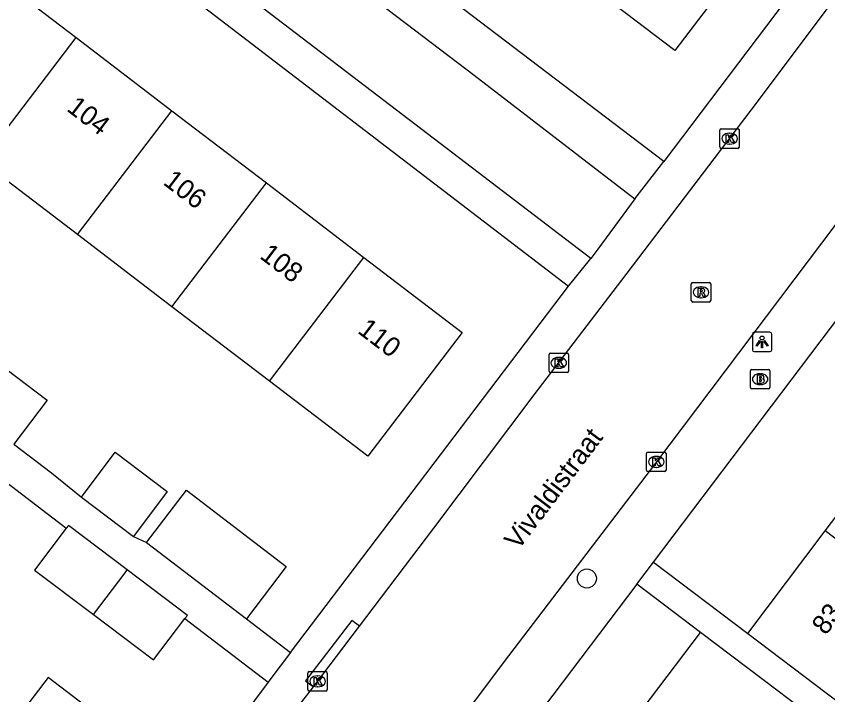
# Model space of a CAD drawing. Extents: x 159040 to 160094, y 381214 to 382518.
# Drawn here: x 159350 to 159391.67, y 381935.45 to 381970.26 of the extents above; entities that cross this region are included whole.
import ezdxf

# ---------------------------------------------------------------- set-up
doc = ezdxf.new("R2010")
doc.units = 0
for name, color, linetype in [('IMGEO_Boom', 7, 'Continuous'), ('IMGEO_Brandkraan', 7, 'Continuous'), ('IMGEO_Kolk', 7, 'Continuous'), ('IMGEO_Lichtpunt', 7, 'Continuous'), ('IMGEO_Openbare_ruimte_label', 7, 'Continuous'), ('IMGEO_Pand', 7, 'Continuous'), ('IMGEO_Pand_nummerreeks', 7, 'Continuous'), ('IMGEO_Rijbaan_lokaal_open', 7, 'Continuous'), ('IMGEO_Rioolput', 7, 'Continuous'), ('IMGEO_Voetpad_open', 7, 'Continuous')]:
    doc.layers.add(name, color=color, linetype=linetype)

msp = doc.modelspace()

# ---------------------------------------------------------------- linework, layer by layer
at = {"layer": 'IMGEO_Boom'}
msp.add_circle((159379.303, 381941.411), 0.489, dxfattribs=at)
at = {"layer": 'IMGEO_Brandkraan'}
for p, q in [((159387.776, 381952.139), (159388.628, 381952.139)), ((159387.701, 381951.213), (159387.701, 381952.065)), ((159388.189, 381951.919), (159388.214, 381951.919)), ((159388.702, 381952.065), (159388.702, 381951.213)), ((159388.212, 381951.359), (159388.187, 381951.359)), ((159388.628, 381951.139), (159387.776, 381951.139))]:
    msp.add_line(p, q, dxfattribs=at)
for points in [[(159387.776, 381952.139), (159388.628, 381952.139)], [(159387.701, 381951.213), (159387.701, 381952.065)], [(159388.049, 381951.839), (159388.049, 381951.439), (159388.262, 381951.439)], [(159388.28, 381951.839), (159388.049, 381951.839)], [(159388.228, 381951.758), (159388.174, 381951.758), (159388.174, 381951.682)], [(159388.702, 381952.065), (159388.702, 381951.213)], [(159388.174, 381951.682), (159388.227, 381951.682)], [(159388.236, 381951.606), (159388.174, 381951.606), (159388.174, 381951.525)], [(159388.174, 381951.525), (159388.236, 381951.525)], [(159388.628, 381951.139), (159387.776, 381951.139)]]:
    msp.add_lwpolyline(points, dxfattribs=at)
for centre, radius, start, end in [((159387.778, 381952.063), 0.0765, 91.552, 178.448), ((159387.778, 381952.063), 0.0765, 91.552, 178.448), ((159388.626, 381952.063), 0.0765, 1.552, 88.448), ((159388.626, 381952.063), 0.0765, 1.552, 88.448), ((159388.229, 381951.72), 0.0379, 267.8285, 90.9355), ((159388.284, 381951.694), 0.145, 59.4692, 91.5367), ((159388.309, 381951.741), 0.0922, 285.5137, 58.1501), ((159388.237, 381951.565), 0.0404, 269.8759, 90.5077), ((159388.268, 381951.69), 0.251, 268.6676, 293.5347), ((159388.314, 381951.549), 0.105, 301.3115, 78.989), ((159387.778, 381951.215), 0.0765, 181.552, 268.448), ((159387.778, 381951.215), 0.0765, 181.552, 268.448), ((159388.626, 381951.215), 0.0765, 271.552, 358.448), ((159388.626, 381951.215), 0.0765, 271.552, 358.448)]:
    msp.add_arc(centre, radius, start, end, dxfattribs=at)
for centre, major_axis, ratio, start_param, end_param in [((159388.188, 381951.639), (-0.387, 0.002), 0.722429, 4.712389, 7.853982), ((159388.213, 381951.639), (-0.39, 0.002), 0.717154, 1.570796, 4.712389)]:
    msp.add_ellipse(centre, major_axis=major_axis, ratio=ratio, start_param=start_param, end_param=end_param, dxfattribs=at)
at = {"layer": 'IMGEO_Kolk'}
for p, q in [((159386.131, 381963.556), (159386.131, 381964.408)), ((159386.206, 381964.482), (159387.058, 381964.482)), ((159386.619, 381964.262), (159386.644, 381964.262)), ((159387.132, 381964.408), (159387.132, 381963.556)), ((159387.058, 381963.482), (159386.206, 381963.482)), ((159386.642, 381963.702), (159386.617, 381963.702)), ((159377.436, 381952.976), (159378.288, 381952.976)), ((159377.361, 381952.05), (159377.361, 381952.902)), ((159377.849, 381952.756), (159377.874, 381952.756)), ((159378.362, 381952.902), (159378.362, 381952.05)), ((159377.872, 381952.196), (159377.847, 381952.196)), ((159378.288, 381951.976), (159377.436, 381951.976)), ((159382.368, 381946.968), (159382.368, 381947.82)), ((159382.443, 381947.894), (159383.295, 381947.894)), ((159382.856, 381947.674), (159382.881, 381947.674)), ((159383.369, 381947.82), (159383.369, 381946.968)), ((159383.295, 381946.894), (159382.443, 381946.894)), ((159382.879, 381947.114), (159382.854, 381947.114)), ((159364.975, 381935.709), (159364.975, 381936.561)), ((159365.05, 381936.635), (159365.902, 381936.635)), ((159365.463, 381936.415), (159365.488, 381936.415)), ((159365.976, 381936.561), (159365.976, 381935.709)), ((159365.902, 381935.635), (159365.05, 381935.635)), ((159365.486, 381935.855), (159365.461, 381935.855))]:
    msp.add_line(p, q, dxfattribs=at)
for points in [[(159386.131, 381963.556), (159386.131, 381964.408)], [(159386.206, 381964.482), (159387.058, 381964.482)], [(159387.132, 381964.408), (159387.132, 381963.556)], [(159386.452, 381964.182), (159386.575, 381964.182), (159386.575, 381964.031), (159386.705, 381964.182), (159386.869, 381964.182), (159386.723, 381964.031), (159386.876, 381963.782), (159386.724, 381963.782), (159386.639, 381963.946), (159386.575, 381963.879), (159386.575, 381963.782), (159386.452, 381963.782), (159386.452, 381964.182)], [(159387.058, 381963.482), (159386.206, 381963.482)], [(159377.436, 381952.976), (159378.288, 381952.976)], [(159377.361, 381952.05), (159377.361, 381952.902)], [(159377.682, 381952.676), (159377.805, 381952.676), (159377.805, 381952.525), (159377.935, 381952.676), (159378.099, 381952.676), (159377.953, 381952.525), (159378.106, 381952.276), (159377.954, 381952.276), (159377.869, 381952.44), (159377.805, 381952.373), (159377.805, 381952.276), (159377.682, 381952.276), (159377.682, 381952.676)], [(159378.362, 381952.902), (159378.362, 381952.05)], [(159378.288, 381951.976), (159377.436, 381951.976)], [(159382.368, 381946.968), (159382.368, 381947.82)], [(159382.443, 381947.894), (159383.295, 381947.894)], [(159382.689, 381947.594), (159382.812, 381947.594), (159382.812, 381947.443), (159382.942, 381947.594), (159383.106, 381947.594), (159382.96, 381947.443), (159383.113, 381947.194), (159382.961, 381947.194), (159382.876, 381947.358), (159382.812, 381947.291), (159382.812, 381947.194), (159382.689, 381947.194), (159382.689, 381947.594)], [(159383.369, 381947.82), (159383.369, 381946.968)], [(159383.295, 381946.894), (159382.443, 381946.894)], [(159364.975, 381935.709), (159364.975, 381936.561)], [(159365.05, 381936.635), (159365.902, 381936.635)], [(159365.296, 381936.335), (159365.419, 381936.335), (159365.419, 381936.184), (159365.549, 381936.335), (159365.713, 381936.335), (159365.567, 381936.184), (159365.72, 381935.935), (159365.568, 381935.935), (159365.483, 381936.099), (159365.419, 381936.032), (159365.419, 381935.935), (159365.296, 381935.935), (159365.296, 381936.335)], [(159365.976, 381936.561), (159365.976, 381935.709)], [(159365.902, 381935.635), (159365.05, 381935.635)]]:
    msp.add_lwpolyline(points, dxfattribs=at)
for centre, start, end in [((159386.208, 381964.406), 91.552, 178.448), ((159386.208, 381964.406), 91.552, 178.448), ((159387.056, 381964.406), 1.552, 88.448), ((159387.056, 381964.406), 1.552, 88.448), ((159386.208, 381963.558), 181.552, 268.448), ((159386.208, 381963.558), 181.552, 268.448), ((159387.056, 381963.558), 271.552, 358.448), ((159387.056, 381963.558), 271.552, 358.448), ((159377.438, 381952.9), 91.552, 178.448), ((159377.438, 381952.9), 91.552, 178.448), ((159378.286, 381952.9), 1.552, 88.448), ((159378.286, 381952.9), 1.552, 88.448), ((159377.438, 381952.052), 181.552, 268.448), ((159377.438, 381952.052), 181.552, 268.448), ((159378.286, 381952.052), 271.552, 358.448), ((159378.286, 381952.052), 271.552, 358.448), ((159382.445, 381947.818), 91.552, 178.448), ((159382.445, 381947.818), 91.552, 178.448), ((159383.293, 381947.818), 1.552, 88.448), ((159383.293, 381947.818), 1.552, 88.448), ((159382.445, 381946.97), 181.552, 268.448), ((159382.445, 381946.97), 181.552, 268.448), ((159383.293, 381946.97), 271.552, 358.448), ((159383.293, 381946.97), 271.552, 358.448), ((159365.052, 381936.559), 91.552, 178.448), ((159365.052, 381936.559), 91.552, 178.448), ((159365.9, 381936.559), 1.552, 88.448), ((159365.9, 381936.559), 1.552, 88.448), ((159365.052, 381935.711), 181.552, 268.448), ((159365.052, 381935.711), 181.552, 268.448), ((159365.9, 381935.711), 271.552, 358.448), ((159365.9, 381935.711), 271.552, 358.448)]:
    msp.add_arc(centre, 0.0765, start, end, dxfattribs=at)
for centre, major_axis, ratio, start_param, end_param in [((159386.618, 381963.982), (-0.387, 0.002), 0.722429, 4.712389, 7.853982), ((159386.643, 381963.982), (-0.39, 0.002), 0.717154, 1.570796, 4.712389), ((159377.848, 381952.476), (-0.387, 0.002), 0.722429, 4.712389, 7.853982), ((159377.873, 381952.476), (-0.39, 0.002), 0.717154, 1.570796, 4.712389), ((159382.855, 381947.394), (-0.387, 0.002), 0.722429, 4.712389, 7.853982), ((159382.88, 381947.394), (-0.39, 0.002), 0.717154, 1.570796, 4.712389), ((159365.462, 381936.135), (-0.387, 0.002), 0.722429, 4.712389, 7.853982), ((159365.487, 381936.135), (-0.39, 0.002), 0.717154, 1.570796, 4.712389)]:
    msp.add_ellipse(centre, major_axis=major_axis, ratio=ratio, start_param=start_param, end_param=end_param, dxfattribs=at)
at = {"layer": 'IMGEO_Lichtpunt'}
for p, q in [((159387.801, 381953.953), (159387.801, 381953.146)), ((159387.801, 381953.953), (159387.801, 381953.146)), ((159388.703, 381954.048), (159387.895, 381954.048)), ((159388.703, 381954.048), (159387.895, 381954.048)), ((159388.797, 381953.146), (159388.797, 381953.953)), ((159388.797, 381953.146), (159388.797, 381953.953)), ((159387.895, 381953.052), (159388.703, 381953.052)), ((159387.895, 381953.052), (159388.703, 381953.052))]:
    msp.add_line(p, q, dxfattribs=at)
for points in [[(159388.175, 381953.617), (159388.214, 381953.589), (159388.026, 381953.327), (159387.988, 381953.354), (159388.175, 381953.617)], [(159388.277, 381953.569), (159388.324, 381953.569), (159388.324, 381953.247), (159388.277, 381953.247), (159388.277, 381953.569)], [(159388.387, 381953.589), (159388.425, 381953.616), (159388.612, 381953.354), (159388.573, 381953.326), (159388.387, 381953.589)]]:
    msp.add_lwpolyline(points, dxfattribs=at)
msp.add_circle((159388.3, 381953.751), 0.0994, dxfattribs=at)
for centre, start, end in [((159387.895, 381953.953), 90, 180), ((159387.895, 381953.953), 90, 180), ((159388.703, 381953.953), 0, 90), ((159388.703, 381953.953), 0, 90), ((159387.895, 381953.146), 180, 270), ((159387.895, 381953.146), 180, 270), ((159388.703, 381953.146), 270, 0), ((159388.703, 381953.146), 270, 360)]:
    msp.add_arc(centre, 0.0946, start, end, dxfattribs=at)
at = {"layer": 'IMGEO_Pand'}
for points in [[(159383.811, 381979.06), (159388.906, 381975.173), (159383.816, 381968.501), (159378.72, 381972.389)], [(159347.407, 381973.488), (159347.838, 381973.159), (159353.074, 381969.165)], [(159348.226, 381962.81), (159353.074, 381969.165)], [(159353.074, 381969.165), (159357.993, 381965.412)], [(159353.145, 381959.057), (159357.993, 381965.412)], [(159357.993, 381965.412), (159362.847, 381961.708)], [(159353.145, 381959.057), (159348.226, 381962.81)], [(159357.999, 381955.354), (159362.847, 381961.708)], [(159362.847, 381961.708), (159367.855, 381957.888)], [(159357.999, 381955.354), (159353.145, 381959.057)], [(159367.855, 381957.888), (159372.898, 381954.04), (159368.05, 381947.686), (159363.007, 381951.533)], [(159363.007, 381951.533), (159367.855, 381957.888)], [(159363.007, 381951.533), (159357.999, 381955.354)], [(159348.463, 381952.919), (159351.588, 381950.556), (159349.879, 381948.295)], [(159391.54, 381943.85), (159395.265, 381948.769)], [(159353.352, 381945.577), (159355.089, 381947.888), (159357.757, 381945.882), (159356.02, 381943.572)], [(159356.692, 381943.254), (159358.738, 381945.935), (159363.866, 381942.023), (159361.82, 381939.341)], [(159353.352, 381945.577), (159356.02, 381943.572)], [(159352.571, 381943.995), (159350.945, 381941.845), (159353.963, 381939.563)], [(159355.707, 381941.849), (159352.679, 381944.138), (159352.571, 381943.995)], [(159387.562, 381938.595), (159391.54, 381943.85)], [(159396.861, 381939.821), (159391.54, 381943.85)], [(159356.692, 381943.254), (159361.82, 381939.341)], [(159353.963, 381939.563), (159355.588, 381941.693), (159355.707, 381941.849)], [(159358.66, 381939.35), (159358.789, 381939.519), (159355.707, 381941.849)], [(159353.963, 381939.563), (159357.045, 381937.233), (159358.66, 381939.35)], [(159381.285, 381933.558), (159385.134, 381938.642)], [(159391.603, 381933.745), (159389.12, 381935.624), (159385.134, 381938.642)], [(159387.562, 381938.595), (159391.585, 381935.549), (159392.883, 381934.567)], [(159344.161, 381926.714), (159349.244, 381922.836), (159354.423, 381929.625), (159356.635, 381932.524), (159351.641, 381936.334), (159349.429, 381933.435), (159349.34, 381933.503)]]:
    msp.add_lwpolyline(points, dxfattribs=at)
at = {"layer": 'IMGEO_Rijbaan_lokaal_open'}
for points in [[(159367.623, 381938.959), (159371.448, 381943.987), (159376.604, 381950.827), (159381.096, 381956.711), (159383.665, 381960.085), (159387.743, 381965.439), (159395.307, 381975.538), (159400.92, 381983.103), (159405.076, 381988.584)], [(159410.86, 381984.24), (159405.257, 381976.785), (159392.08, 381959.597), (159382.82, 381947.331), (159375.274, 381937.448), (159369.627, 381929.935), (159365.099, 381923.996), (159363.697, 381922.105)], [(159354.4, 381981.799), (159364.253, 381974.292), (159373.522, 381967.236), (159381.764, 381960.886)], [(159379.509, 381957.83), (159352.11, 381978.74), (159352.56, 381979.34)], [(159381.764, 381960.886), (159379.871, 381958.305), (159379.509, 381957.83)], [(159365.26, 381935.852), (159367.623, 381938.959)], [(159358.041, 381926.414), (159361.248, 381930.665), (159364.911, 381935.394), (159365.26, 381935.852)]]:
    msp.add_lwpolyline(points, dxfattribs=at)
at = {"layer": 'IMGEO_Rioolput'}
for p, q in [((159384.663, 381955.67), (159384.663, 381956.522)), ((159384.738, 381956.596), (159385.59, 381956.596)), ((159385.151, 381956.376), (159385.176, 381956.376)), ((159385.664, 381956.522), (159385.664, 381955.67)), ((159385.59, 381955.596), (159384.738, 381955.596)), ((159385.174, 381955.816), (159385.149, 381955.816))]:
    msp.add_line(p, q, dxfattribs=at)
for points in [[(159384.663, 381955.67), (159384.663, 381956.522)], [(159384.738, 381956.596), (159385.59, 381956.596)], [(159385.252, 381956.294), (159385, 381956.296), (159385, 381955.896)], [(159385.664, 381956.522), (159385.664, 381955.67)], [(159385, 381955.896), (159385.124, 381955.896), (159385.124, 381956.058), (159385.135, 381956.058)], [(159385.178, 381956.215), (159385.124, 381956.215), (159385.124, 381956.134)], [(159385.124, 381956.134), (159385.176, 381956.134)], [(159385.182, 381956.029), (159385.253, 381955.896), (159385.393, 381955.896), (159385.328, 381956.022)], [(159385.59, 381955.596), (159384.738, 381955.596)]]:
    msp.add_lwpolyline(points, dxfattribs=at)
for centre, radius, start, end in [((159384.74, 381956.52), 0.0765, 91.552, 178.448), ((159384.74, 381956.52), 0.0765, 91.552, 178.448), ((159385.588, 381956.52), 0.0765, 1.552, 88.448), ((159385.588, 381956.52), 0.0765, 1.552, 88.448), ((159385.134, 381956.005), 0.0533, 26.0293, 88.6989), ((159385.16, 381956.323), 0.19, 274.7715, 282.9687), ((159385.184, 381956.119), 0.0964, 77.0061, 93.1865), ((159385.198, 381956.176), 0.0378, 276.6634, 79.6772), ((159385.251, 381956.184), 0.109, 350.3612, 89.416), ((159385.249, 381956.184), 0.112, 277.5842, 350.9817), ((159385.233, 381955.969), 0.108, 29.5134, 73.7905), ((159384.74, 381955.672), 0.0765, 181.552, 268.448), ((159384.74, 381955.672), 0.0765, 181.552, 268.448), ((159385.588, 381955.672), 0.0765, 271.552, 358.448), ((159385.588, 381955.672), 0.0765, 271.552, 358.448)]:
    msp.add_arc(centre, radius, start, end, dxfattribs=at)
for centre, major_axis, ratio, start_param, end_param in [((159385.15, 381956.096), (-0.387, 0.002), 0.722429, 4.712389, 7.853982), ((159385.175, 381956.096), (-0.39, 0.002), 0.717154, 1.570796, 4.712389)]:
    msp.add_ellipse(centre, major_axis=major_axis, ratio=ratio, start_param=start_param, end_param=end_param, dxfattribs=at)
at = {"layer": 'IMGEO_Voetpad_open'}
for points in [[(159383.263, 381962.809), (159355.809, 381983.682)], [(159397.577, 381981.74), (159383.263, 381962.809)], [(159350.613, 381977.649), (159378.352, 381956.413)], [(159381.764, 381960.886), (159383.263, 381962.809)], [(159382.726, 381942.256), (159397.868, 381962.257)], [(159378.352, 381956.413), (159379.509, 381957.83)], [(159364.085, 381937.613), (159378.352, 381956.413)], [(159349.879, 381948.295), (159351.809, 381946.835), (159353.352, 381945.577)], [(159348.939, 381946.765), (159352.395, 381944.129), (159352.571, 381943.995)], [(159356.02, 381943.572), (159356.692, 381943.254)], [(159381.864, 381941.117), (159382.726, 381942.256)], [(159382.726, 381942.256), (159387.562, 381938.595)], [(159381.864, 381941.117), (159358.765, 381910.606)], [(159385.134, 381938.642), (159381.864, 381941.117)], [(159358.66, 381939.35), (159362.932, 381936.091)], [(159361.82, 381939.341), (159364.085, 381937.613)], [(159367.623, 381938.959), (159367.227, 381939.263), (159364.864, 381936.156), (159365.26, 381935.852)], [(159364.085, 381937.613), (159363.026, 381936.217), (159362.932, 381936.091)], [(159362.932, 381936.091), (159349.407, 381917.941), (159348.619, 381918.534)]]:
    msp.add_lwpolyline(points, dxfattribs=at)

# ---------------------------------------------------------------- texts
at = {"layer": 'IMGEO_Openbare_ruimte_label'}
msp.add_text('Vivaldistraat', height=1, rotation=52.9239, dxfattribs=at).set_placement((159375.784, 381942.828))
at = {"layer": 'IMGEO_Pand_nummerreeks'}
for s, rotation, p in [('104', 322.659, (159352.539, 381965.447)), ('106', 322.659, (159357.495, 381961.666)), ('108', 322.659, (159362.454, 381957.883)), ('110', 322.659, (159367.482, 381954.047)), ('83', 52.872, (159391.571, 381938.457))]:
    msp.add_text(s, height=1, rotation=rotation, dxfattribs=at).set_placement(p)

doc.saveas('drawing.dxf')
